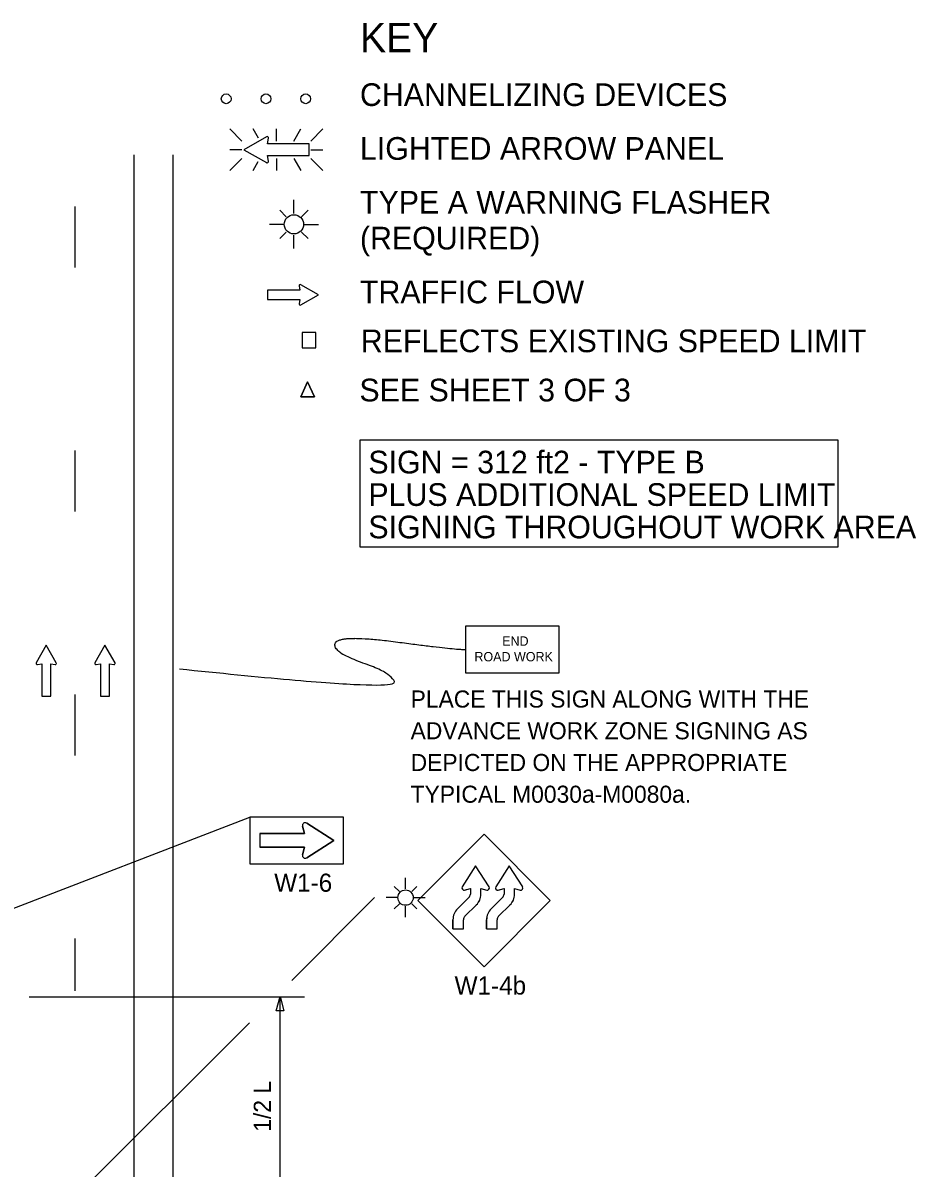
# Model space of a CAD drawing. Extents: x 16726 to 19504, y 5932 to 7446.
# Drawn here: x 17077.3 to 17443.4, y 6450.1 to 6919.3 of the extents above; entities that cross this region are included whole.
import ezdxf

# ---------------------------------------------------------------- set-up
doc = ezdxf.new("R2010")
doc.units = 0
for name, color, linetype in [('ALI_LEGAL_EX', 7, 'Continuous'), ('MT_SCRATCH_LEVEL_E', 7, 'Continuous'), ('PAVT_EDGE_EX', 7, 'Continuous'), ('TRAFFIC_SIGNS_PR', 7, 'Continuous'), ('TYPICAL_TEXT_DIMEN_EX', 7, 'Continuous'), ('TYPICAL_TEXT_DIMEN_PR', 7, 'Continuous')]:
    doc.layers.add(name, color=color, linetype=linetype)

msp = doc.modelspace()

# ---------------------------------------------------------------- linework, layer by layer
at = {"layer": 'ALI_LEGAL_EX'}
for points in [[(17098.71, 6819.12), (17098.71, 6844.12)], [(17098.71, 6719.12), (17098.71, 6744.12)], [(17098.71, 6619.12), (17098.71, 6644.12)], [(17098.71, 6522.64), (17098.71, 6544.12)]]:
    msp.add_lwpolyline(points, dxfattribs=at)
at = {"layer": 'MT_SCRATCH_LEVEL_E'}
for p, q in [((17190.81, 6809.78), (17177.56, 6809.78)), ((17177.56, 6809.78), (17177.56, 6806.04)), ((17190.81, 6809.78), (17177.56, 6809.78)), ((17177.56, 6809.78), (17177.56, 6806.04)), ((17190.5, 6811.56), (17190.81, 6809.78)), ((17190.5, 6811.56), (17190.81, 6809.78)), ((17198.42, 6807.93), (17191.18, 6812.04)), ((17198.42, 6807.93), (17191.18, 6812.04)), ((17177.56, 6806.04), (17190.81, 6806.04)), ((17177.56, 6806.04), (17190.81, 6806.04)), ((17190.81, 6806.04), (17190.5, 6804.26)), ((17190.81, 6806.04), (17190.5, 6804.26)), ((17191.18, 6803.78), (17198.42, 6807.93)), ((17191.18, 6803.78), (17198.42, 6807.93)), ((17086.85, 6664.37), (17082.74, 6657.13)), ((17086.85, 6664.37), (17082.74, 6657.13)), ((17090.99, 6657.13), (17086.85, 6664.37)), ((17090.99, 6657.13), (17086.85, 6664.37)), ((17110.92, 6664.37), (17106.81, 6657.13)), ((17110.92, 6664.37), (17106.81, 6657.13)), ((17115.07, 6657.13), (17110.92, 6664.37)), ((17115.07, 6657.13), (17110.92, 6664.37)), ((17083.22, 6656.44), (17085, 6656.76)), ((17083.22, 6656.44), (17085, 6656.76)), ((17085, 6656.76), (17085, 6643.5)), ((17085, 6656.76), (17085, 6643.5)), ((17088.74, 6643.5), (17088.74, 6656.76)), ((17088.74, 6656.76), (17090.52, 6656.44)), ((17088.74, 6643.5), (17088.74, 6656.76)), ((17088.74, 6656.76), (17090.52, 6656.44)), ((17107.29, 6656.44), (17109.07, 6656.76)), ((17107.29, 6656.44), (17109.07, 6656.76)), ((17109.07, 6656.76), (17109.07, 6643.5)), ((17109.07, 6656.76), (17109.07, 6643.5)), ((17112.81, 6643.5), (17112.81, 6656.76)), ((17112.81, 6656.76), (17114.59, 6656.44)), ((17112.81, 6643.5), (17112.81, 6656.76)), ((17112.81, 6656.76), (17114.59, 6656.44)), ((17085, 6643.5), (17088.74, 6643.5)), ((17085, 6643.5), (17088.74, 6643.5)), ((17109.07, 6643.5), (17112.81, 6643.5)), ((17109.07, 6643.5), (17112.81, 6643.5))]:
    msp.add_line(p, q, dxfattribs=at)
for centre, start, end in [((17190.96, 6811.63), 60.4248, 189.9638), ((17190.96, 6811.63), 60.4248, 189.9638), ((17190.96, 6804.19), 170.0362, 299.7731), ((17190.96, 6804.19), 170.0362, 299.7731), ((17083.14, 6656.9), 150.4248, 279.9638), ((17083.14, 6656.9), 150.4248, 279.9638), ((17090.59, 6656.9), 260.0362, 29.7731), ((17090.59, 6656.9), 260.0362, 29.7731), ((17107.22, 6656.9), 150.4248, 279.9638), ((17107.22, 6656.9), 150.4248, 279.9638), ((17114.66, 6656.9), 260.0362, 29.7731), ((17114.66, 6656.9), 260.0362, 29.7731)]:
    msp.add_arc(centre, 0.463, start, end, dxfattribs=at)
at = {"layer": 'PAVT_EDGE_EX'}
for p, q in [((17122.71, 6865.32), (17122.71, 6079.93)), ((17138.71, 6865.32), (17138.71, 6112.72))]:
    msp.add_line(p, q, dxfattribs=at)
at = {"layer": 'TRAFFIC_SIGNS_PR'}
for p, q in [((17162.11, 6875.87), (17167.04, 6870.93)), ((17173.87, 6872.04), (17171.66, 6875.87)), ((17181.19, 6870.93), (17181.19, 6875.87)), ((17188.42, 6870.93), (17191.27, 6875.87)), ((17195.34, 6870.93), (17200.27, 6875.87)), ((17167.04, 6867.38), (17162.11, 6867.38)), ((17195.34, 6867.38), (17200.27, 6867.38)), ((17162.11, 6858.89), (17167.04, 6863.82)), ((17171.62, 6858.89), (17173.73, 6862.55)), ((17181.19, 6863.82), (17181.19, 6858.89)), ((17191.32, 6858.89), (17188.47, 6863.82)), ((17195.34, 6863.82), (17200.27, 6858.88)), ((17188.39, 6841.21), (17188.39, 6846.84)), ((17188.39, 6841.21), (17188.39, 6846.84)), ((17185.25, 6839.91), (17182.62, 6842.55)), ((17185.25, 6839.91), (17182.62, 6842.55)), ((17191.53, 6839.91), (17194.16, 6842.55)), ((17191.53, 6839.91), (17194.16, 6842.55)), ((17184.45, 6836.78), (17178.42, 6836.78)), ((17184.45, 6836.78), (17178.42, 6836.78)), ((17185.25, 6833.64), (17182.62, 6831.01)), ((17185.25, 6833.64), (17182.62, 6831.01)), ((17191.53, 6833.64), (17194.16, 6831.01)), ((17191.53, 6833.64), (17194.16, 6831.01)), ((17192.33, 6836.78), (17198.42, 6836.78)), ((17192.33, 6836.78), (17198.42, 6836.78)), ((17188.39, 6826.83), (17188.39, 6832.34)), ((17188.39, 6826.83), (17188.39, 6832.34)), ((17192.78, 6587.13), (17191.94, 6590.19)), ((17193.62, 6591.43), (17204.78, 6584.33)), ((17174.38, 6587.13), (17192.78, 6587.13)), ((17174.38, 6587.13), (17174.38, 6581.53)), ((17204.78, 6584.33), (17193.62, 6577.23)), ((17266.31, 6586.9), (17239.15, 6559.75)), ((17293.46, 6559.75), (17266.31, 6586.9)), ((17192.78, 6581.53), (17174.38, 6581.53)), ((17191.94, 6578.47), (17192.78, 6581.53)), ((17231.64, 6563.41), (17229.53, 6565.52)), ((17234.15, 6564.45), (17234.15, 6568.95)), ((17236.67, 6563.41), (17238.77, 6565.52)), ((17231, 6560.9), (17226.16, 6560.9)), ((17237.31, 6560.9), (17242.19, 6560.9)), ((17255.44, 6556.28), (17260.15, 6561)), ((17260.15, 6560.99), (17255.44, 6556.28)), ((17269.24, 6556.28), (17273.95, 6561)), ((17273.95, 6560.99), (17269.24, 6556.28)), ((17231.64, 6558.38), (17229.53, 6556.27)), ((17234.15, 6552.93), (17234.15, 6557.34)), ((17236.67, 6558.38), (17238.77, 6556.28)), ((17239.15, 6559.75), (17266.31, 6532.59)), ((17258.49, 6553.23), (17263.21, 6557.94)), ((17258.49, 6553.23), (17263.21, 6557.94)), ((17266.31, 6532.59), (17293.46, 6559.75)), ((17272.29, 6553.23), (17277, 6557.94)), ((17272.29, 6553.23), (17277, 6557.94)), ((17253.57, 6548.16), (17253.57, 6551.86)), ((17257.89, 6548.16), (17257.89, 6551.86)), ((17267.37, 6548.16), (17267.37, 6551.86)), ((17271.69, 6548.16), (17271.69, 6551.86)), ((17253.57, 6548.16), (17257.89, 6548.16)), ((17267.37, 6548.16), (17271.69, 6548.16))]:
    msp.add_line(p, q, dxfattribs=at)
for points in [[(17177.12, 6872.65), (17167.82, 6867.38), (17177.12, 6862.06)], [(17177.99, 6862.68), (17177.59, 6864.95), (17194.6, 6864.95), (17194.6, 6869.75), (17177.59, 6869.75), (17177.99, 6872.03)], [(17194.02, 6772.24), (17191.23, 6766.07)], [(17191.23, 6766.07), (17194.02, 6772.24)], [(17196.82, 6766.07), (17194.02, 6772.24)], [(17194.02, 6772.24), (17196.82, 6766.07)], [(17191.23, 6766.07), (17196.82, 6766.07)], [(17196.82, 6766.07), (17191.23, 6766.07)], [(17191.94, 6590.19), (17192.78, 6587.13), (17174.38, 6587.13), (17174.38, 6581.53), (17192.78, 6581.53), (17191.94, 6578.47)], [(17193.62, 6577.23), (17204.78, 6584.33), (17193.62, 6591.43)], [(17268.36, 6565.27), (17262.88, 6573.88), (17257.4, 6565.27)], [(17268.36, 6565.27), (17262.88, 6573.88), (17257.4, 6565.27)], [(17282.16, 6565.27), (17276.67, 6573.88), (17271.19, 6565.27)], [(17282.16, 6565.27), (17276.67, 6573.88), (17271.19, 6565.27)], [(17258.36, 6563.97), (17260.72, 6564.62), (17260.71, 6562.33)], [(17258.36, 6563.97), (17259.19, 6564.2), (17260.72, 6564.62), (17260.71, 6562.33)], [(17265.03, 6562.25), (17265.03, 6564.62), (17267.4, 6563.97)], [(17265.03, 6562.25), (17265.03, 6564.62), (17267.4, 6563.97)], [(17272.15, 6563.97), (17274.51, 6564.62), (17274.51, 6562.33)], [(17272.15, 6563.97), (17272.99, 6564.2), (17274.51, 6564.62), (17274.51, 6562.33)], [(17278.83, 6562.25), (17278.83, 6564.62), (17281.19, 6563.97)], [(17278.83, 6562.25), (17278.83, 6564.62), (17281.19, 6563.97)], [(17253.57, 6551.86), (17253.57, 6548.16), (17257.89, 6548.16), (17257.89, 6551.86)], [(17267.37, 6551.86), (17267.37, 6548.16), (17271.69, 6548.16), (17271.69, 6551.86)]]:
    msp.add_lwpolyline(points, dxfattribs=at)
for points in [[(17191.8, 6786.22), (17197.4, 6786.22), (17197.4, 6792.4), (17191.8, 6792.4)], [(17258.77, 6652.97), (17297.17, 6652.97), (17297.17, 6672.17), (17258.77, 6672.17)], [(17170.38, 6574.73), (17208.78, 6574.73), (17208.78, 6593.93), (17170.38, 6593.93)]]:
    msp.add_lwpolyline(points, close=True, dxfattribs=at)
for centre, radius in [((17160.62, 6888.22), 2), ((17176.92, 6888.22), 2), ((17193.22, 6888.22), 2), ((17188.39, 6836.78), 3.94), ((17188.39, 6836.78), 3.94), ((17234.15, 6560.89), 3.15)]:
    msp.add_circle(centre, radius, dxfattribs=at)
for centre, radius, start, end in [((17177.4, 6872.13), 0.598, 350.7308, 118.8916), ((17177.4, 6862.58), 0.597, 241.4833, 9.9593), ((17193.02, 6590.49), 1.12, 57.5304, 195.3269), ((17193.02, 6590.49), 1.12, 57.5304, 195.3269), ((17193.02, 6578.17), 1.12, 164.6731, 302.4696), ((17193.02, 6578.17), 1.12, 164.6731, 302.4696), ((17258.13, 6564.81), 0.864, 147.5204, 285.3986), ((17258.13, 6564.81), 0.866, 147.5288, 285.3852), ((17267.63, 6564.81), 0.866, 254.6828, 32.2708), ((17267.63, 6564.81), 0.866, 254.6799, 32.2804), ((17277.47, 6571.07), 10.8, 212.4569, 212.4665), ((17271.92, 6564.81), 0.864, 147.5204, 285.3986), ((17271.92, 6564.81), 0.866, 147.5288, 285.3852), ((17281.42, 6564.81), 0.866, 254.6828, 32.2708), ((17281.42, 6564.81), 0.866, 254.6799, 32.2804), ((17291.27, 6571.07), 10.8, 212.4569, 212.4665), ((17258.86, 6562.32), 1.85, 314.2123, 0.1238), ((17258.86, 6562.32), 1.85, 314.2125, 0), ((17258.86, 6562.32), 6.17, 314.2125, 359.3819), ((17258.86, 6562.32), 6.17, 314.7687, 359.3755), ((17264.54, 6553.55), 10.8, 74.68, 74.6808), ((17272.66, 6562.32), 1.85, 314.2123, 0.1238), ((17272.66, 6562.32), 1.85, 314.2125, 0), ((17272.66, 6562.32), 6.17, 314.2125, 359.3819), ((17272.66, 6562.32), 6.17, 314.7687, 359.3755), ((17278.34, 6553.55), 10.8, 74.68, 74.6808), ((17259.74, 6551.86), 6.17, 134.2125, 180), ((17259.74, 6551.86), 6.17, 134.2125, 180), ((17259.74, 6551.86), 6.17, 134.2117, 180), ((17273.53, 6551.86), 6.17, 134.2125, 180), ((17273.53, 6551.86), 6.17, 134.2125, 180), ((17273.54, 6551.86), 6.17, 134.2117, 180), ((17259.74, 6551.86), 1.85, 132.372, 180), ((17259.74, 6551.86), 1.85, 134.2125, 180), ((17273.53, 6551.86), 1.85, 134.2125, 180), ((17273.54, 6551.86), 1.85, 132.372, 180)]:
    msp.add_arc(centre, radius, start, end, dxfattribs=at)
at = {"layer": 'TYPICAL_TEXT_DIMEN_EX'}
msp.add_lwpolyline([(17215.57, 6748.42), (17411.3, 6748.42), (17411.3, 6704.51), (17215.57, 6704.51)], close=True, dxfattribs=at)
at = {"layer": 'TYPICAL_TEXT_DIMEN_PR'}
for p, q in [((16985.82, 6522.8), (17170.38, 6593.93)), ((17221.48, 6560.9), (17187.5, 6526.96)), ((17192.7, 6520.14), (17079.87, 6520.14)), ((17181.14, 6514.51), (17182.71, 6520.37)), ((17182.71, 6520.37), (17184.28, 6514.51)), ((17182.71, 6440.47), (17182.71, 6520.14)), ((17182.71, 6514.51), (17181.14, 6514.51)), ((17184.28, 6514.51), (17182.71, 6514.51)), ((17170.12, 6509.61), (17036.34, 6376.02))]:
    msp.add_line(p, q, dxfattribs=at)
msp.add_open_spline([(17141.46, 6654.61), (17229.37, 6645.4), (17229.37, 6652.66), (17203.92, 6661.44), (17206.76, 6668.84), (17253.84, 6662.57), (17258.77, 6662.57)], degree=2, dxfattribs=at)

# ---------------------------------------------------------------- texts
at = {"layer": 'TRAFFIC_SIGNS_PR'}
for s, height, p in [('END', 3.831, (17273.77, 6664.1)), ('ROAD WORK', 3.831, (17262.38, 6657.71)), ('PLACE THIS SIGN ALONG WITH THE', 7, (17236.23, 6638.77)), ('ADVANCE WORK ZONE SIGNING AS', 7, (17236.23, 6625.77)), ('DEPICTED ON THE APPROPRIATE', 7, (17236.23, 6612.77)), ('TYPICAL M0030a-M0080a.', 7, (17236.23, 6599.77)), ('W1-6', 7.44, (17180.32, 6563.29)), ('W1-4b', 7.44, (17254.26, 6521.16))]:
    msp.add_text(s, height=height, dxfattribs=at).set_placement(p)
at = {"layer": 'TYPICAL_TEXT_DIMEN_EX'}
for s, height, p in [('KEY', 12, (17215.46, 6907.33)), ('CHANNELIZING DEVICES', 9.3, (17215.46, 6885.28)), ('LIGHTED ARROW PANEL', 9.3, (17215.46, 6863.23)), ('TYPE A WARNING FLASHER', 9.3, (17215.46, 6841.18)), ('(REQUIRED)', 9.3, (17215.46, 6826.48)), ('TRAFFIC FLOW', 9.3, (17215.46, 6804.43)), ('REFLECTS EXISTING SPEED LIMIT', 9.3, (17215.8, 6784.39)), ('SEE SHEET 3 OF 3', 9.3, (17215.23, 6764.23)), ('SIGN = 312 ft2 - TYPE B', 9.3, (17218.91, 6734.71)), ('PLUS ADDITIONAL SPEED LIMIT', 9.3, (17218.91, 6721.41)), ('SIGNING THROUGHOUT WORK AREA', 9.3, (17218.91, 6708.11))]:
    msp.add_text(s, height=height, dxfattribs=at).set_placement(p)
at = {"layer": 'TYPICAL_TEXT_DIMEN_PR'}
msp.add_text('1/2 L', height=7, rotation=90, dxfattribs=at).set_placement((17178.93, 6464.96))

doc.saveas('drawing.dxf')
